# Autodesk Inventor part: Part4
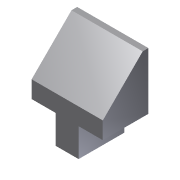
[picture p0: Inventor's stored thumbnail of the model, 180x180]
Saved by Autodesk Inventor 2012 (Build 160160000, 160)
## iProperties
Shininess: 77.0
Length Units: 11269
Angle Units: 11279
Time Units: 11290
Mass Units: 11283
Length Display Precision: 3
Angle Display Precision: 2
Created: 2002-01
Part Number: Part4
Document SubType Name: Modeling
Designer: ***
Density: 1 g/cm^3
Material: Default
Density: 0.0
Volumn: 0.0
Area: 0.0
PropertySet Name: Model Information
Control State: 0
Master: False
Checked Out: False
Author: ***
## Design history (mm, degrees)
sketch "Sketch2"
  geometry: L1 (2.32, -6.969)-(2.32, 13.031); L2 (2.32, 13.031)-(0.32, 13.031); L3 (0.32, 13.031)-(-13.68, -0.969); L4 (-13.68, -0.969)-(-13.68, -6.969); L5 (-13.68, -6.969)-(2.32, -6.969)
  constraints: 10 end point, 2 parallel, 1 perpendicular, 1 vertical
  dimensions: "d0" = 2 distance of L1.end L2.end; "d1" = 135 deg angle of L4 L3; "d2" = 20 distance of L1.start L1.end; "d3" = 16 distance of L4.end L1.start
extrude "Extrusion1" new body sketch "Sketch2" stored distance "d4" = 25; taper "d5" = 0 deg
sketch "Sketch3"
  geometry: L1 (-13.68, -6.969)-(2.32, -6.969); L2 (2.32, -6.969)-(2.32, -16.969); L3 (2.32, -16.969)-(-13.68, -16.969); L4 (-13.68, -16.969)-(-13.68, -6.969); L5 (-13.68, -6.969)-(2.32, -6.969) reference; L6 (-13.68, -0.969)-(-13.68, -6.969) reference; L7 (2.32, -6.969)-(2.32, 13.031) reference
  constraints: 8 end point, 3 collinear, 2 parallel, 1 horizontal, 1 perpendicular
  dimensions: "d6" = 10 distance of L3.end L1.start
extrude "Extrusion2" join sketch "Sketch3" stored distance "d7" = 8; taper "d8" = 0 deg
body "Solid1"
